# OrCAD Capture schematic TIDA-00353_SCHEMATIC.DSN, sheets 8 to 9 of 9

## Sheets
8 PAGE7 LMK: size B; note: LMK
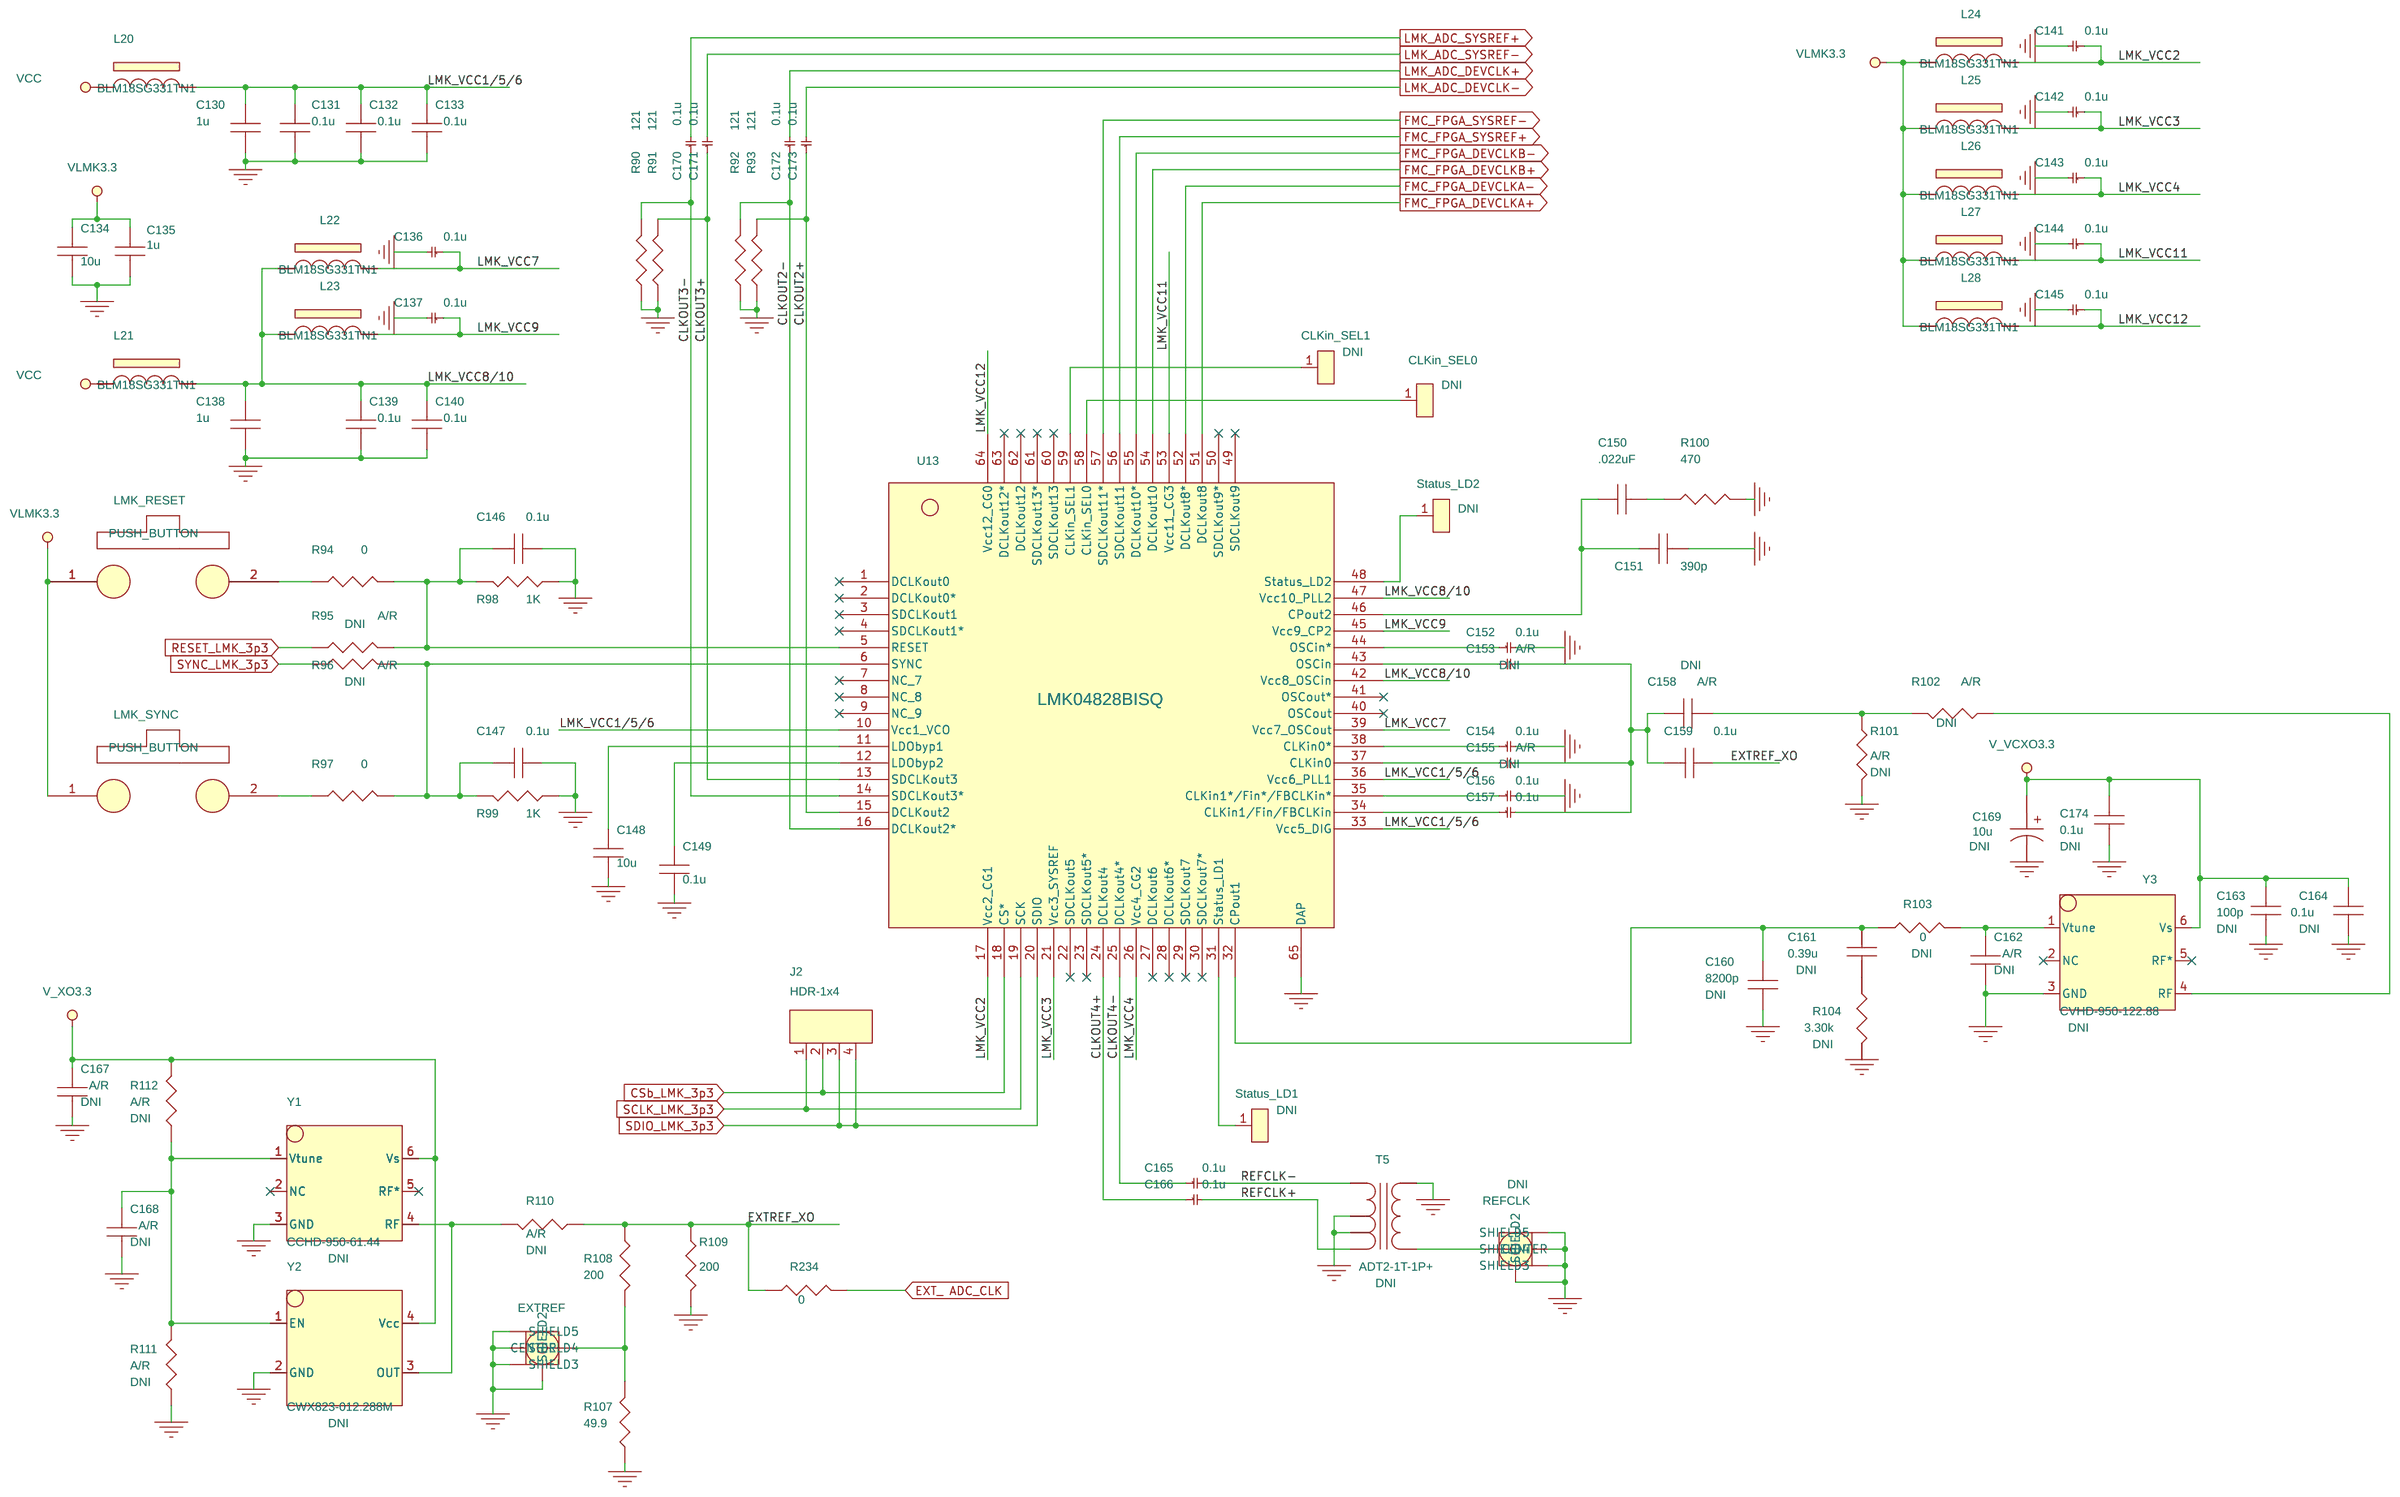
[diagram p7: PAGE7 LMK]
9 PAGE4 ADC: size B; note: ADC
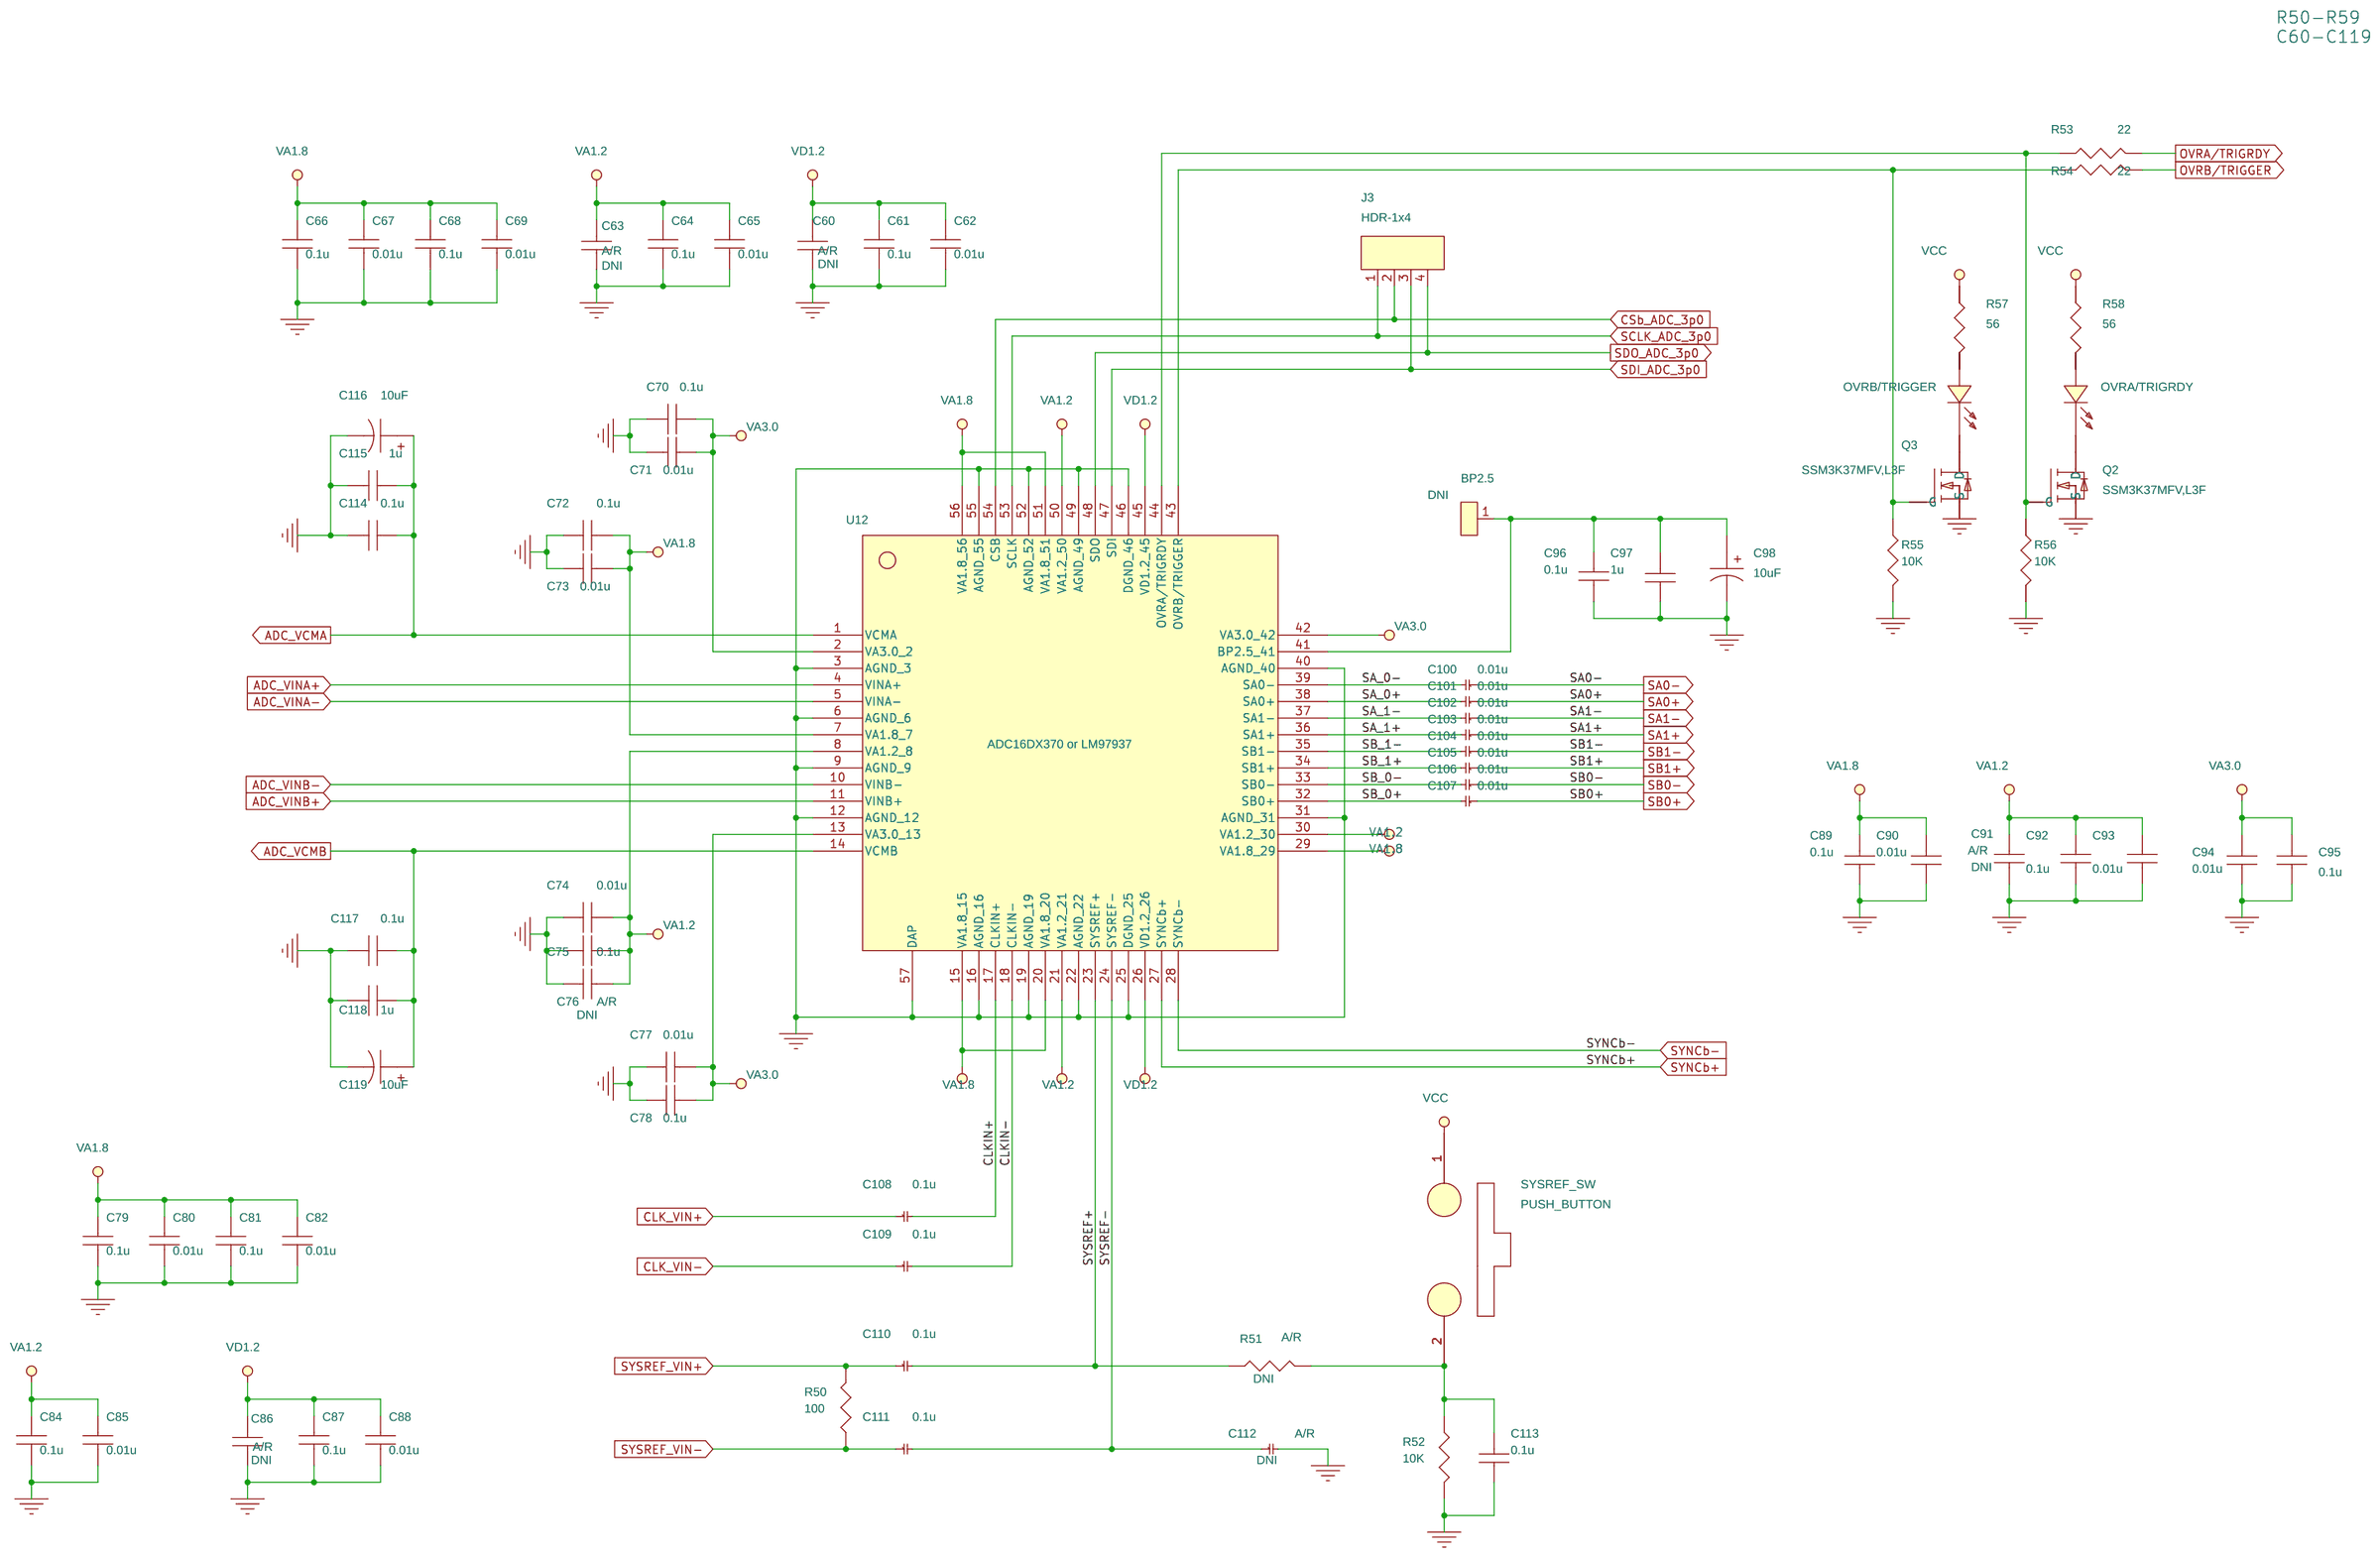
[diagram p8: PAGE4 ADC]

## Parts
sheet PAGE4 ADC
BP2.5  HDR-1x1_0  [tp_500x_50]
C60  A/R  [C0402_NO_SS]
C61  0.1u  [C0402_NO_SS]
C62  0.01u  [0201]
C63  A/R  [C0402_NO_SS]
C64  0.1u  [C0402_NO_SS]
C65  0.01u  [0201]
C66  0.1u  [C0402_NO_SS]
C67  0.01u  [0201]
C68  0.1u  [C0402_NO_SS]
C69  0.01u  [0201]
C70  0.1u  [C0402_NO_SS]
C71  0.01u  [0201]
C72  0.1u  [C0402_NO_SS]
C73  0.01u  [0201]
C74  0.01u  [0201]
C75  0.1u  [C0402_NO_SS]
C76  A/R  [C0402_NO_SS]
C77  0.01u  [0201]
C78  0.1u  [C0402_NO_SS]
C79  0.1u  [C0402_NO_SS]
C80  0.01u  [0201]
C81  0.1u  [C0402_NO_SS]
C82  0.01u  [0201]
C84  0.1u  [C0402_NO_SS]
C85  0.01u  [0201]
C86  A/R  [C0402_NO_SS]
C87  0.1u  [C0402_NO_SS]
C88  0.01u  [0201]
C89  0.1u  [C0402_NO_SS]
C90  0.01u  [0201]
C91  A/R  [C0402_NO_SS]
C92  0.1u  [C0402_NO_SS]
C93  0.01u  [0201]
C94  0.01u  [0201]
C95  0.1u  [C0402_NO_SS]
C96  0.1u  [C0402_NO_SS]
C97  1u  [0508]
C98  10uF  [cap_a-case]
C100  0.01u  [0201]
C101  0.01u  [0201]
C102  0.01u  [0201]
C103  0.01u  [0201]
C104  0.01u  [0201]
C105  0.01u  [0201]
C106  0.01u  [0201]
C107  0.01u  [0201]
C108  0.1u  [0201]
C109  0.1u  [0201]
C110  0.1u  [0201]
C111  0.1u  [0201]
C112  A/R  [0201]
C113  0.1u  [smd_size0402]
C114  0.1u  [0201]
C115  1u  [0508]
C116  10uF  [cap_a-case]
C117  0.1u  [0201]
C118  1u  [0508]
C119  10uF  [cap_a-case]
J3  HDR-1x4  [blkcon_4x1]
OVRA/TRIGRDY  LED  [LED_0805]
OVRB/TRIGGER  LED  [LED_0805]
Q2  SSM3K37MFV,L3F  [sot-723]
Q3  SSM3K37MFV,L3F  [sot-723]
R50  100  [0201]
R51  A/R  [0201]
R52  10K  [C0402_NO_SS]
R53  22  [C0402_NO_SS]
R54  22  [C0402_NO_SS]
R55  10K  [C0402_NO_SS]
R56  10K  [C0402_NO_SS]
R57  56  [smd_size0402]
R58  56  [smd_size0402]
SYSREF_SW  PUSH_BUTTON  [evqppd]
U12  ADC16DX370 or LM97937  [qfn56_0p5]
sheet PAGE7 LMK
C130  1u  [C0402_NO_SS]
C131  0.1u  [C0402_NO_SS]
C132  0.1u  [C0402_NO_SS]
C133  0.1u  [C0402_NO_SS]
C134  10u  [0805]
C135  1u  [C0402_NO_SS]
C136  0.1u  [C0402_NO_SS]
C137  0.1u  [C0402_NO_SS]
C138  1u  [C0402_NO_SS]
C139  0.1u  [C0402_NO_SS]
C140  0.1u  [C0402_NO_SS]
C141  0.1u  [C0402_NO_SS]
C142  0.1u  [C0402_NO_SS]
C143  0.1u  [C0402_NO_SS]
C144  0.1u  [C0402_NO_SS]
C145  0.1u  [C0402_NO_SS]
C146  0.1u  [smd_size0402]
C147  0.1u  [smd_size0402]
C148  10u  [0805]
C149  0.1u  [C0402_NO_SS]
C150  .022uF  [0603]
C151  390p  [0603]
C152  0.1u  [C0402_NO_SS]
C153  A/R  [C0402_NO_SS]
C154  0.1u  [C0402_NO_SS]
C155  A/R  [C0402_NO_SS]
C156  0.1u  [C0402_NO_SS]
C157  0.1u  [C0402_NO_SS]
C158  A/R  [C0402_NO_SS]
C159  0.1u  [C0402_NO_SS]
C160  8200p  [0603]
C161  0.39u  [0603]
C162  A/R  [C0402_NO_SS]
C163  100p  [0603]
C164  0.1u  [0603]
C165  0.1u  [C0402_NO_SS]
C166  0.1u  [C0402_NO_SS]
C167  A/R  [C0402_NO_SS]
C168  A/R  [C0402_NO_SS]
C169  10u  [smd_size3216]
C170  0.1u  [C0402_NO_SS]
C171  0.1u  [C0402_NO_SS]
C172  0.1u  [C0402_NO_SS]
C173  0.1u  [C0402_NO_SS]
C174  0.1u  [0603]
CLKin_SEL0  HDR-1x1_0  [tp_500x_50]
CLKin_SEL1  HDR-1x1_0  [tp_500x_50]
EXTREF  CLK_DIFF  [con_sma-edge]
J2  HDR-1x4  [blkcon_4x1]
L20  INDUCTOR FERRITE/SM  [r0603]
L21  INDUCTOR FERRITE/SM  [r0603]
L22  INDUCTOR FERRITE/SM  [r0603]
L23  INDUCTOR FERRITE/SM  [r0603]
L24  INDUCTOR FERRITE/SM  [r0603]
L25  INDUCTOR FERRITE/SM  [r0603]
L26  INDUCTOR FERRITE/SM  [r0603]
L27  INDUCTOR FERRITE/SM  [r0603]
L28  INDUCTOR FERRITE/SM  [r0603]
LMK_RESET  PUSH_BUTTON  [evqppd]
LMK_SYNC  PUSH_BUTTON  [evqppd]
R90  121  [C0402_NO_SS]
R91  121  [C0402_NO_SS]
R92  121  [C0402_NO_SS]
R93  121  [C0402_NO_SS]
R94  0  [C0402_NO_SS]
R95  A/R  [C0402_NO_SS]
R96  A/R  [C0402_NO_SS]
R97  0  [C0402_NO_SS]
R98  1K  [smd_size0402]
R99  1K  [smd_size0402]
R100  470  [0603]
R101  A/R  [C0402_NO_SS]
R102  A/R  [C0402_NO_SS]
R103  0  [0603]
R104  3.30k  [0603]
R107  49.9  [C0402_NO_SS]
R108  200  [C0402_NO_SS]
R109  200  [C0402_NO_SS]
R110  A/R  [C0402_NO_SS]
R111  A/R  [C0402_NO_SS]
R112  A/R  [C0402_NO_SS]
R234  0  [C0402_NO_SS]
REFCLK  CLK_DIFF  [con_sma-edge]
Status_LD1  HDR-1x1_0  [tp_500x_50]
Status_LD2  HDR-1x1_0  [tp_500x_50]
T5  ADT2-1T-1P+  [ADT1-1WT]
U13  LMK04828BISQ  [sc-mkt-sqa64a]
Y1  CCHD-950-61.44  [soic6_100_wg272_l560]
Y2  CWX823-012.288M  [CWX813]
Y3  CVHD-950-122.88  [soic6_100_wg272_l560]

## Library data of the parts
BP2.5 = HDR-1x1_2: Manufactured by: Keystone; Note: DNI; Part Number: 5005
C60 C63 C76 C86 C91 = CAPACITOR_NON-POL: Note: DNI
C61 C64 C66 C68 C70 C72 C75 C78 C79 C81 C84 C87 C89 C92 C95 C96 C131-C133 C139 C140 C149 C159 = Cap_1: Distributed by: Digikey; Distributor Part #: 490-5415-1-ND; Manufactured by: Murata Electronics North America; Part Description: CAP CER .1UF 16V X5R 0402; Part Number: GRM155R61C104KA88D
C62 C65 C67 C69 C71 C73 C74 C77 C80 C82 C85 C88 C90 C93 C94 = Cap_1: Distributed by: Digikey; Distributor Part #: 490-3194-1-ND; Manufactured by: Murata Electronics North America; Part Description: CAP CER 10000PF 10V X7R 0201; Part Number: GRM033R71A103KA01D
C97 C115 C118 = Capacitor_4: Distributed by: Digikey; Distributor Part #: 445-1809-1-ND; MFR's P/N: C1220X5R1A105K; Manufactured by: TDK Corporation; Part Description: CAP CER 1.0UF 10V 10% X5R 0508; Part Number: C1220X5R1A105M085AC
C98 C116 C119 = Cap_Polar_1: Distributed by: Digikey; Distributor Part #: 478-3859-1-ND; Manufactured by: AVX Corporation; Part Description: CAP TANTALUM 10UF 16V 20% SMD; Part Number: TAJA106M016RNJ
C100-C107 = C-NON-POL: Distributed by: Digikey; Distributor Part #: 490-3194-1-ND; Manufactured by: Murata Electronics North America; Part Description: CAP CER 10000PF 10V X7R 0201; Part Number: GRM033R71A103KA01D
C108-C111 = C-NON-POL: Distributed by: Digikey; Distributor Part #: 490-3167-1-ND; Manufactured by: Murata Electronics North America; Part Description: CAP CER 0.1UF 6.3V 10% X5R 0201; Part Number: GRM033R60J104KE19D
C112 C153 C155 = C-NON-POL: Note: DNI
C113 C146 C147 = Capacitor_3: Distributed by: Digikey; Distributor Part #: 490-5415-1-ND; Manufactured by: Murata Electronics North America; Part Description: CAP CER 0.1UF 16V 10% X5R 0402; Part Number: GRM155R61C104KA88D
C114 C117 = Capacitor_4: Distributed by: Digikey; Distributor Part #: 490-3167-1-ND; Manufactured by: Murata Electronics North America; Part Description: CAP CER 0.1UF 6.3V 10% X5R 0201; Part Number: GRM033R60J104KE19D
J2 J3 = HDR-1x4_0
OVRA/TRIGRDY OVRB/TRIGGER = LED: Green LED; Distributed by: Digikey; Distributor Part #: 160-1414-1-ND; Manufactured by: LITEON; Manufaturer: LITEON; Mfr Prt #: LTST-C170KGKT; Mfr_Name: Liteon; Mfr_Part_Number: LTST-C170KGKT; Package: SMD; Part Description: LED GREEN CLEAR 0805 SMD; Part Number: LTST-C170KGKT; Terasic_Prt: M0200
Q2 Q3 = BSS138_SOT: Distributed by: Digikey; Distributor Part #: SSM3K37MFVL3FCT-ND; Manufactured by: Toshiba; Part Description: MOSFET N-CH 20V 250MA VESM
R50 = Resistor_3: Distributed by: Digikey; Distributor Part #: P100ABCT-ND; Manufactured by: Panasonic Electronic Components; Part Description: RES 100 OHM 1/20W 1% 0201 SMD; Part Number: ERJ-1GEF1000C
R51 R95 R96 R110-R112 = Resistor_3: Note: DNI
R52 R55 R56 = Resistor_3: Distributed by: Digikey; Distributor Part #: 541-10.0KLCT-ND; Manufactured by: Vishay Dale; Part Description: RES 10.0K OHM 1/16W 1% 0402 SMD; Part Number: CRCW040210K0FKED
R53 R54 = Resistor_3: Distributed by: Digikey; Distributor Part #: P22.0LCT-ND; MFR's P/N: RC0402JR-070RL; Manufactured by: Panasonic Electronic Components; Part Description: RES 22.0 OHM 1/10W 1% 0402 SMD; Part Number: ERJ-2RKF22R0X
R57 R58 = Resistor_3: Distributed by: Digikey; Distributor Part #: P56JCT-ND; Manufactured by: Panasonic - ECG; Part Description: RES 56 OHM 1/10W 5% 0402 SMD; Part Number: ERJ-2GEJ560X
LMK_RESET LMK_SYNC SYSREF_SW = PUSH_BUTTON_0: Distributed by: Digikey; Distributor Part #: CKN9076CT-ND; Manufactured by: C&K Components; Part Description: SWITCH TACTILE SPST-NO 0.05A 12V; Part Number: PTS635SK25SMTR LFS
U12 = LM97937_SOCKET_4: Manufactured by: Texas Instruments; Part Number: ADC16DX370
C130 C135 C138 = CAPACITOR_NON-POL: Distributed by: Digikey; Distributor Part #: 445-4114-1-ND; Manufactured by: TDK Corporation; Part Description: CAP CER 1UF 10V 10% X5R 0402; Part Number: C1005X5R1A105K
C134 C148 = Cap_1: Distributed by: Digikey; Distributor Part #: 445-5985-1-ND; Manufactured by: Samsung Electro-Mechanics America, Inc; Part Description: CAP CER 10UF 25V 20% X5R 0805; Part Number: CL21B106KOQNNNE
C136 C137 C141-C145 C152 C154 C156 C157 C165 C166 C170-C173 = C-NON-POL: Distributed by: Digikey; Distributor Part #: 490-5415-1-ND; Manufactured by: Murata Electronics North America; Part Description: CAP CER .1UF 16V X5R 0402; Part Number: GRM155R61C104KA88D
C150 = Capacitor_4: Distributed by: Digikey; Distributor Part #: 445-2669-1-ND; Manufactured by: Kemet; Part Description: CAP CER 0.022UF 25V 5% X7R 0603; Part Number: C0603C223J3RACTU
C151 = Capacitor_4: Distributed by: Digikey; Distributor Part #: 478-1168-1-ND; Manufactured by: AVX Corporation; Part Description: CAP CER 390PF 50V 5% NP0 0603; Part Number: 06035A391JAT2A
C158 C162 C168 = Cap_1: Note: DNI
C160 = Capacitor_4: Distributed by: Digikey; Distributor Part #: 445-2668-1-ND; Manufactured by: TDK Corporation; Note: DNI; Part Description: CAP CER 8200PF 25V 5% NP0 0603; Part Number: C1608C0G1E822J
C161 = Capacitor_4: Distributed by: Digikey; Distributor Part #: 399-4919-1-ND; Manufactured by: Kemet; Note: DNI; Part Description: CAP CER 0.39UF 16V 10% X7R 0603; Part Number: C0603C394K4RACTU
C163 = Capacitor_4: Distributed by: Digikey; Distributor Part #: 445-1281-1-ND; Manufactured by: TDK Corporation; Note: DNI; Part Description: CAP CER 100PF 50V 5% NP0 0603; Part Number: C1608C0G1H101J
C164 C174 = Capacitor_4: Distributed by: Digikey; Distributor Part #: 478-1239-1-ND; Manufactured by: AVX Corporation; Note: DNI; Part Description: CAP CERM .1UF 10% 16V X7R 0603; Part Number: 0603YC104KAT2A
C167 = Capacitor_4: Note: DNI
C169 = Cap_Polar_1: Distributed by: Digikey; Distributor Part #: 478-3859-1-ND; Manufactured by: AVX Corporation; Note: DNI; Part Description: CAP TANT 10UF 16V 20% 1206; Part Number: TAJA106M016RNJ
CLKin_SEL0 CLKin_SEL1 Status_LD1 Status_LD2 = HDR-1x1_2: Note: DNI
EXTREF = SMA_CONN_5: Distributed by: Digikey; Distributor Part #: J658-ND; MFR's P/N: 142-0701-851; Manufactured by: Johnson; Part Description: CONN JACK END LAUNCH PC GOLD SMA; Part Number: 142-0701-851
L20-L28 = INDUCTOR_FERRITE_SM: Murata Ferrite Bead SM 1.5A; Distributed by: Digikey; Distributor Part #: 490-3997-1-ND; Manufactured by: Murata Electronics North America; Manufacturer Part Number: BLM18SG331TN1; Part Description: FILTER CHIP 330 OHM 1.5A 0603; Part Number: BLM18SG331TN1D
R90-R93 = Resistor_3: Distributed by: Digikey; Distributor Part #: 541-121LCT-ND; Manufactured by: Vishay Dale; Part Description: RES 121 OHM 1/16W 1% 0402 SMD; Part Number: CRCW0402121RFKED
R94 R97 = Resistor_3: Distributed by: Digikey; Distributor Part #: P0.0JCT-ND; MFR's P/N: ERJ-2GE0R00X; Manufactured by: Panasonic; Part Description: RES 0.0 OHM 1/10W JUMP 0402 SMD; Part Number: ERJ-2GE0R00X
R98 R99 = Resistor_3: Distributed by: Digikey; Distributor Part #: P1.00KLCT-ND; Manufactured by: Panasonic - ECG; Part Description: RES 1.00K OHM 1/10W 1% 0402 SMD; Part Number: ERJ-2RKF1001X
R100 = Resistor_3: Distributed by: Digikey; Distributor Part #: 311-560HRCT-ND; Manufactured by: Yageo; Part Description: RES 470 OHM 1/10W 1% 0603 SMD; Part Number: RC0603FR-07470RL
R101 R102 = Resistor_3: Distributed by: Digikey; Distributor Part #: 541-200LCT-ND; Manufactured by: Vishay Dale; Note: DNI; Part Description: RES 200 OHM 1/16W 1% 0402 SMD; Part Number: CRCW0402200RFKED
R103 = Resistor_3: Distributed by: Digikey; Distributor Part #: P0.0GCT-ND; Manufactured by: Panasonic Electronic Components; Note: DNI; Part Description: RES 0.0 OHM 1/10W 0603 SMD; Part Number: ERJ-3GEY0R00V
R104 = Resistor_3: Distributed by: Digikey; Distributor Part #: 311-3.30KHRCT-ND; Manufactured by: Yageo; Note: DNI; Part Description: RES 3.30K OHM 1/10W 1% 0603 SMD; Part Number: RC0603FR-073K3L
R107 = Resistor_3: Distributed by: Digikey; Distributor Part #: P49.9LCT-ND; MFR's P/N: ERJ-2RKF49R9X; Manufactured by: Panasonic - ECG; Part Description: RES 49.9 OHM 1/10W 1% 0402 SMD; Part Number: ERJ-2RKF49R9X
R108 R109 = Resistor_3: Distributed by: Digikey; Distributor Part #: 541-200LCT-ND; Manufactured by: Vishay Dale; Part Description: RES 200 OHM 1/16W 1% 0402 SMD; Part Number: CRCW0402200RFKED
R234 = Resistor_3: Distributed by: Digikey; Distributor Part #: 311-0.0JRCT-ND; MFR's P/N: RC0402JR-070RL; Manufactured by: Yageo; Part Description: RES 0.0 OHM 1/16W 0402 SMD; Part Number: RC0402JR-070RL
REFCLK = SMA_CONN_5: Distributed by: Digikey; Distributor Part #: J658-ND; MFR's P/N: 142-0701-851; Manufactured by: Johnson; Note: DNI; Part Description: CONN JACK END LAUNCH PC GOLD SMA; Part Number: 142-0701-851
T5 = ADT2-1T-1P+_0: Distributed by: Mini-Circuits; Manufactured by: Mini-Circuits; Note: DNI; Part Description: Surface Mount RF Transformer 50 Ohm 8 to 600 MHz
U13 = LMK04828BISQ: Manufactured by: Texas Instrument; Part Description: Low-Noise Clock Jitter Cleaner with Dual Loop PLLs
Y1 = CCHD-950-61.44: Distributed by: Mouser; Distributor Part #: 549-CCHD-950-25-61.4; Manufactured by: Crystek Corporation; Note: DNI; Part Description: Standard Clock Oscillators 9X14 25PPM 3.3V HCMOS; Part Number: CCHD-950-25-61.440
Y2 = CWX823-012.288M: Distributed by: Digikey; Distributor Part #: CW439TR-ND; Manufactured by: Connor-Winfield; Note: DNI; Part Description: OSC 12.2880MHZ 3.3V +-50PPM SMD
Y3 = CVHD-950-122.88: Distributed by: Digikey; Distributor Part #: 744-1271-ND; Manufactured by: Crystek Corporation; Note: DNI; Part Description: VCXO CMOS 122.880 MHZ 3.3V SMD; Part Number: CVHD-950-122.880

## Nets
GND: C60.1 C61.2 C62.2 C63.1 C64.2 C65.2 C66.2 C67.2 C68.2 C69.2 C70.2 C71.2 C72.1 C73.1 C74.1 C75.1 C76.1 C77.1 C78.1 C79.2 C80.2 C81.2 C82.2 C84.2 C85.2 C86.1 C87.2 C88.2 C89.1 C90.1 C91.2 C92.2 C93.2 C94.1 C95.1 C96.2 C97.1 C98.2 C112.2 C113.1 C114.2 C115.2 C116.2 C117.2 C118.2 C119.2 C130.2 C131.2 C132.2 C133.2 C134.2 C135.2 C136.2 C137.2 C138.2 C139.2 C140.2 C141.2 C142.2 C143.2 C144.2 C145.2 C146.1 C147.1 C148.2 C149.2 C151.2 C152.2 C154.2 C156.2 C160.2 C162.2 C163.2 C164.2 C167.2 C168.2 C169.2 C174.2 EXTREF.2(SHIELD2) EXTREF.3(SHIELD3) EXTREF.4(SHIELD4) EXTREF.5(SHIELD5) Q2.2(S) Q3.2(S) R52.2 R55.1 R56.1 R90.1 R91.1 R92.1 R93.1 R98.2 R99.2 R100.2 R101.1 R104.2 R107.1 R109.1 R111.1 REFCLK.2(SHIELD2) REFCLK.3(SHIELD3) REFCLK.4(SHIELD4) REFCLK.5(SHIELD5) T5.2 T5.3 T5.5 U12.3(AGND) U12.6(AGND) U12.9(AGND) U12.12(AGND) U12.16(AGND) U12.19(AGND) U12.22(AGND) U12.25(DGND) U12.31(AGND) U12.40(AGND) U12.46(DGND) U12.49(AGND) U12.52(AGND) U12.55(AGND) U12.57(DAP) U13.65(DAP) Y1.3(GND) Y2.2(GND) Y3.3(GND) ; also on sheet 1 2 3 4 5 6 7
ADC_VCMA: C114.1 C115.1 C116.1 U12.1(VCMA) ; also on sheet 3
ADC_VCMB: C117.1 C118.1 C119.1 U12.14(VCMB) ; also on sheet 3
ADC_VINA+: U12.4(VINA+) ; also on sheet 3
ADC_VINA-: U12.5(VINA-) ; also on sheet 3
ADC_VINB+: U12.11(VINB+) ; also on sheet 3
ADC_VINB-: U12.10(VINB-) ; also on sheet 3
CLK_VIN+: C108.1 ; also on sheet 1
CLK_VIN-: C109.1 ; also on sheet 1
CLKIN+: C108.2 U12.17(CLKIN+)
CLKIN-: C109.2 U12.18(CLKIN-)
CLKOUT2+: C173.1 R93.2 U13.15(DCLKout2)
CLKOUT2-: C172.1 R92.2 U13.16(DCLKout2*)
CLKOUT3+: C171.1 R91.2 U13.13(SDCLKout3)
CLKOUT3-: C170.1 R90.2 U13.14(SDCLKout3*)
CLKOUT4+: C166.1 U13.24(DCLKout4)
CLKOUT4-: C165.1 U13.25(DCLKout4*)
CSb_ADC_3p0: J3.2 U12.54(CSB) ; also on sheet 6 7
CSb_LMK_3p3: J2.2 U13.18(CS*) ; also on sheet 6
EXT_ ADC_CLK: R234.2 ; also on sheet 1
EXTREF_XO: C159.1 R108.2 R109.2 R110.1 R234.1
FMC_FPGA_DEVCLKA+: U13.51(DCLKout8) ; also on sheet 7
FMC_FPGA_DEVCLKA-: U13.52(DCLKout8*) ; also on sheet 7
FMC_FPGA_DEVCLKB+: U13.54(DCLKout10) ; also on sheet 7
FMC_FPGA_DEVCLKB-: U13.55(DCLKout10*) ; also on sheet 7
FMC_FPGA_SYSREF+: U13.56(SDCLKout11) ; also on sheet 7
FMC_FPGA_SYSREF-: U13.57(SDCLKout11*) ; also on sheet 7
LMK_ADC_DEVCLK+: C172.2 ; also on sheet 1
LMK_ADC_DEVCLK-: C173.2 ; also on sheet 1
LMK_ADC_SYSREF+: C170.2 ; also on sheet 1
LMK_ADC_SYSREF-: C171.2 ; also on sheet 1
LMK_VCC1/5/6: C130.1 C131.1 C132.1 C133.1 L20.1 U13.10(Vcc1_VCO) U13.33(Vcc5_DIG) U13.36(Vcc6_PLL1)
LMK_VCC2: C141.1 L24.2 U13.17(Vcc2_CG1)
LMK_VCC3: C142.1 L25.2 U13.21(Vcc3_SYSREF)
LMK_VCC4: C143.1 L26.2 U13.26(Vcc4_CG2)
LMK_VCC7: C136.1 L22.2 U13.39(Vcc7_OSCout)
LMK_VCC8/10: C138.1 C139.1 C140.1 L21.1 L22.1 L23.1 U13.42(Vcc8_OSCin) U13.47(Vcc10_PLL2)
LMK_VCC9: C137.1 L23.2 U13.45(Vcc9_CP2)
LMK_VCC11: C144.1 L27.2 U13.53(Vcc11_CG3)
LMK_VCC12: C145.1 L28.2 U13.64(Vcc12_CG0)
OVRA/TRIGRDY: R53.2 ; also on sheet 7
OVRB/TRIGGER: R54.2 ; also on sheet 7
REFCLK+: C166.2 T5.6
REFCLK-: C165.2 T5.4
RESET_LMK_3p3: R95.1 ; also on sheet 6
SA0+: C101.1 ; also on sheet 7
SA0-: C100.1 ; also on sheet 7
SA1+: C103.1 ; also on sheet 7
SA1-: C102.1 ; also on sheet 7
SA_0+: C101.2 U12.38(SA0+)
SA_0-: C100.2 U12.39(SA0-)
SA_1+: C103.2 U12.36(SA1+)
SA_1-: C102.2 U12.37(SA1-)
SB0+: C107.1 ; also on sheet 7
SB0-: C106.1 ; also on sheet 7
SB1+: C105.1 ; also on sheet 7
SB1-: C104.1 ; also on sheet 7
SB_0+: C107.2 U12.32(SB0+)
SB_0-: C106.2 U12.33(SB0-)
SB_1+: C105.2 U12.34(SB1+)
SB_1-: C104.2 U12.35(SB1-)
SCLK_ADC_3p0: J3.1 U12.53(SCLK) ; also on sheet 6 7
SCLK_LMK_3p3: J2.1 U13.19(SCK) ; also on sheet 6
SDI_ADC_3p0: J3.3 U12.47(SDI) ; also on sheet 6 7
SDIO_LMK_3p3: J2.3 J2.4 U13.20(SDIO) ; also on sheet 6
SDO_ADC_3p0: J3.4 U12.48(SDO) ; also on sheet 6 7
SYNC_LMK_3p3: R96.1 ; also on sheet 6
SYNCb+: U12.27(SYNCb+) ; also on sheet 7
SYNCb-: U12.28(SYNCb-) ; also on sheet 7
SYSREF+: C110.2 R51.1 U12.23(SYSREF+)
SYSREF-: C111.2 C112.1 U12.24(SYSREF-)
SYSREF_VIN+: C110.1 R50.2 ; also on sheet 1
SYSREF_VIN-: C111.1 R50.1 ; also on sheet 1
V_VCXO3.3: C163.1 C164.1 C169.1 C174.1 Y3.6(Vs) ; also on sheet 5
V_XO3.3: C167.1 R112.2 Y1.6(Vs) Y2.4(Vcc) ; also on sheet 5
VA1.2: C63.2 C64.1 C65.1 C74.2 C75.2 C76.2 C84.1 C85.1 C91.1 C92.1 C93.1 SYSREF_SW.1 U12.8(VA1.2) U12.21(VA1.2) U12.30(VA1.2) U12.50(VA1.2) ; also on sheet 5
VA1.8: C66.1 C67.1 C68.1 C69.1 C72.2 C73.2 C79.1 C80.1 C81.1 C82.1 C89.2 C90.2 U12.7(VA1.8) U12.15(VA1.8) U12.20(VA1.8) U12.29(VA1.8) U12.51(VA1.8) U12.56(VA1.8) ; also on sheet 5
VA3.0: C70.1 C71.1 C77.2 C78.2 C94.2 C95.2 U12.2(VA3.0) U12.13(VA3.0) U12.42(VA3.0) ; also on sheet 5
VA3.0_LED: R57.2 R58.2 ; also on sheet 5 6 7
VD1.2: C60.2 C61.1 C62.1 C86.2 C87.1 C88.1 U12.26(VD1.2) U12.45(VD1.2) ; also on sheet 5
VLMK3.3: C134.1 C135.1 L20.2 L21.2 L24.1 L25.1 L26.1 L27.1 L28.1 LMK_RESET.1 LMK_SYNC.1 ; also on sheet 4 5 6
N17204057: C162.1 R103.2 Y3.1(Vtune)
N17204061: C160.1 C161.1 R103.1 U13.32(CPout1)
N17204110: REFCLK.1(CENTER) T5.1
N17204122: C149.1 U13.12(LDObyp2)
N17204150: R110.2 Y1.4(RF) Y2.3(OUT)
N17204206: C148.1 U13.11(LDObyp1)
N17204360: EXTREF.1(CENTER) R107.2 R108.1
N17204562: C150.1 C151.1 U13.46(CPout2)
N17204592: C150.2 R100.1
N17204632: R102.2 Y3.4(RF)
N17204638: C158.2 R101.2 R102.1
N17204674: C168.1 R111.2 R112.1 Y1.1(Vtune) Y2.1(EN)
N17204744: C152.1 U13.44(OSCin*)
N17262131: BP2.5.1 C96.1 C97.2 C98.1 U12.41(BP2.5)
N17267182: C147.2 R96.2 R97.2 R99.1 U13.6(SYNC)
N17403168: OVRA/TRIGRDY.1(ANODE) R58.1
N17405429: OVRB/TRIGGER.1(ANODE) R57.1
N17407540: Q2.1(G) R53.1 R56.2 U12.44(OVRA/TRIGRDY)
N17407548: Q3.1(G) R54.1 R55.2 U12.43(OVRB/TRIGGER)
N17461045: Status_LD2.1 U13.48(Status_LD2)
N17467440: C153.2 C155.2 C157.2 C158.1 C159.2
N17467450: C153.1 U13.43(OSCin)
N17467802: C156.1 U13.35(CLKin1*/Fin*/FBCLKin*)
N17467807: C157.1 U13.34(CLKin1/Fin/FBCLKin)
N17467978: C154.1 U13.38(CLKin0*)
N17467983: C155.1 U13.37(CLKin0)
N17471425: Status_LD1.1 U13.31(Status_LD1)
N17477944: CLKin_SEL1.1 U13.59(CLKin_SEL1)
N17492975: C146.2 R94.2 R95.2 R98.1 U13.5(RESET)
N17497915: LMK_RESET.2 R94.1
N17498425: LMK_SYNC.2 R97.1
N17525558: CLKin_SEL0.1 U13.58(CLKin_SEL0)
N17567551: C113.2 R51.2 R52.1 SYSREF_SW.2
N18025719: C161.2 R104.1
N18030782: OVRA/TRIGRDY.2(CATHODE) Q2.3(D)
N18030783: OVRB/TRIGGER.2(CATHODE) Q3.3(D)

Not connected (* = marked no-connect by the designer): U13 1(DCLKout0)* 2(DCLKout0*)* 3(SDCLKout1)* 4(SDCLKout1*)* 7(NC)* 8(NC)* 9(NC)* 22(SDCLKout5)* 23(SDCLKout5*)* 27(DCLKout6)* 28(DCLKout6*)* 29(SDCLKout7)* 30(SDCLKout7*)* 40(OSCout)* 41(OSCout*)* 49(SDCLKout9)* 50(SDCLKout9*)* 60(SDCLKout13)* 61(SDCLKout13*)* 62(DCLKout12)* 63(DCLKout12*)*; Y1 2(NC)* 5(RF*)*; Y3 2(NC)* 5(RF*)*

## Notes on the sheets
sheet 9
- R50-R59
  C60-C119
